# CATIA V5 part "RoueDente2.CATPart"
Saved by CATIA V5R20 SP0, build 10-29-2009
Part number: engrenage
Source: Unknown
Publications: "Esquisse.8", "Plan.3"
Material "Rouge DS": density 7860 kg/m3, Young's modulus 2e+11 Pa, Poisson ratio 0.266
Bounding box of the stored display mesh (mm): x -5 to 5, y -11.489 to 11.489, z -11.419 to 11.495
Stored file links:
  E:\EDELI\gcausse\Edeli_2012_233_gcausse\RoueDente2.CATPart
  C:\usr\gt1\projet\site_web\doc\catia\gears\spur_gear_files\parts\gear_n.CATPart
  C:\Users\thinkmotion1\Desktop\Nouveau dossier\Cremai_Automobile\Cremaillere_automobile.CATProduct
  C:\Program Files\Dassault Systemes\B20\win_b64\startup\materials\French\Catalog.CATMaterial
  C:\Program Files\Dassault Systemes\B20\win_b64\startup\materials\red_env_512x512.jpg
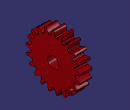
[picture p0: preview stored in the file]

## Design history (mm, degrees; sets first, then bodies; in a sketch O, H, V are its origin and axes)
Parameters
  a = 20 deg
  m = 1 mm
  Z = 21
  rp = 10.5 mm {= m * Z / 2}
  ra = 11.5 mm {= rp + m}
  rb = 9.8668 mm {= rp * cos( a )}
  rf = 9.25 mm {= rp - 1.25 * m}
  rc = 0.38 mm {= m * 0.38}
  c = 0.115855 {= sqrt( 1 / ( cos( a ) * cos( a ) ) - 1 ) / PI}
  phi = 5.1397 deg
  `diametre perçages extérieurs` = 35 mm
Set1
  DatumCurve1: linked copy from another document
Set2
  Line1 "Axe X": stored without definition
  Plane1: type Angle, RefPlane zx-plane, Direction Line1, Angle 8.5714 {= 180deg / Z}
  Point1 "origine": (0, 0, 0)
  Point2: (0, 0, 9.8668)
  Point3: (0, 0.101, 10.3417)
  Point4: (0, 0.7841, 11.6263)
  Point5: (0, 2.5164, 13.3228)
  Point6: (0, 5.5524, 14.8411)
  Curve1: Elements (Point2; Point3; Point4; Point5; Point6)
  Extrapol1: ToExtrapol Point2, Support Curve1, Length 2 {= m * 2}
  Rotate1: Axis Line1, Angle 5.1397 {= phi}, ToTransfor Extrapol1
  Circle1: type CtrRad, Start 0, End 180, Center Point1, Support yz-plane, Radius 9.25 {= rf}, FirstDirection (0, 1, 0)
  Circle2: type CtrRad, Start 0, End 180, Center Point1, Support yz-plane, Radius 11.5 {= ra}, FirstDirection (0, 1, 0)
  Corner1: Element1 Rotate1, Element2 Circle1, Radius 0.38 {= rc}
  Symmetry1: Reference Plane1, ToTransfor Corner1
  Split1: ToCut Rotate1, Cutting (Corner1; Circle2)
  Symmetry2: Reference zx-plane, ToTransfor Split1
  Circle3: type 2PointsRad, Start 0, End 180, FirstPoint vertex of Symmetry1, SecondPoint vertex of Corner1, Support yz-plane, Radius 9.25 {= rf}
  Circle4: type 2PointsRad, Start 0, End 180, FirstPoint vertex of Split1, SecondPoint vertex of Symmetry2, Support yz-plane, Radius 11.5 {= ra}
  Join1: Elements (Symmetry1; Circle3; Corner1; Split1; Circle4; Symmetry2)
  CircPattern1: of Join1, instances 21 {= Z}, angular step 17.1429 {= 360.0*1 deg/CircPattern1.AngularNumber}, axis from Line1
  Join2: Elements (Join1; CircPattern1)
  Plane2: type Offset, RefPlane yz-plane, Offset 33
  Sketch1 on start face of Pad1, origin (0, 0, 0), H (0, -1, 0), V (0, 0, 1)
    circle A1 centre (0, 0) radius 2.5
    radius A1 = 2.5
Body1 (main body)
  Pad1: profile Join2, length 5
  Sketch2 on Plane2, origin (33, 0, 0), H (0, 1, 0), V (0, 0, 1)
    circle A1 centre (0, 0) radius 31.6677
    radius A1 = 31.6677
  Pocket1: profile Sketch1, direction (1, 0, 0), length 30
  Sketch3 on start face of Pad1, origin (0, 0, 0), H (0, -1, 0), V (0, 0, 1)
    circle A1 centre (5.6921, 1.8974) radius 2.5
    point P1 (5.6921, 1.8974)
    radius A1 = 2.5
    distance P1 O = 6
  Pad2: profile Sketch3, direction (-1, 0, 0), length 5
